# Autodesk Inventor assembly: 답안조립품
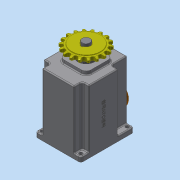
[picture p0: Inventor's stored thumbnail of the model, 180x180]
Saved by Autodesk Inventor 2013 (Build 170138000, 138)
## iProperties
Created: 2017-12
Part Number: 답안조립품
Document SubType Name: Assembly
Designer: dgall
Mass: 1781.57 g
Surface Area: 2015.56 cm^2
Volume: 734.129 cm^3
Density: 2.42678 g/cm^3
Author: dgall
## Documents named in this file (17)
- C:\Users\dgall\Desktop\371207V1016\답안조립품.iam
- C:\Users\dgall\Desktop\371207V1016\본체.ipt
- C:\Users\dgall\Desktop\371207V1016\서브축.ipt
- C:\Users\dgall\Desktop\371207V1016\베어링 608.ipt
- C:\Users\dgall\Desktop\371207V1016\베어링 6003.ipt
- C:\Users\dgall\Desktop\371207V1016\키 5 x 5 x 18.ipt
- C:\Users\dgall\Desktop\371207V1016\커버.ipt
- C:\Users\dgall\Desktop\371207V1016\오일 실 17 32 8.ipt
- C:\Users\dgall\Desktop\371207V1016\메인축.ipt
- C:\Users\dgall\Desktop\371207V1016\스프로킷.ipt
- C:\Users\dgall\Desktop\371207V1016\멈춤나사 M3x8.ipt
- C:\Users\dgall\Desktop\371207V1016\가변스프링.ipt
- C:\Users\dgall\Desktop\371207V1016\부시.ipt
- C:\Users\dgall\Desktop\371207V1016\슬라이더.ipt
- C:\Users\dgall\Desktop\371207V1016\상부 캡.ipt
- C:\Users\dgall\Desktop\371207V1016\오일 실 8 22 7.ipt
- C:\Users\dgall\Desktop\371207V1016\볼트 M4 x 10.ipt
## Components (1 placed, 1 different names)
1. 가변스프링:1
